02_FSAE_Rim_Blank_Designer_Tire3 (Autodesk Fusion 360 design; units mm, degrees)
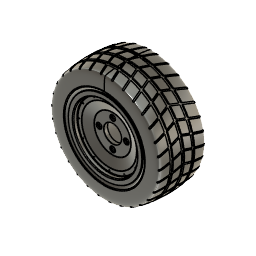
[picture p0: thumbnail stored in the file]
part number: 2026-07-27-09-56-27-671
sketch "Sketch1" plane through (0, 0, 0) normal (1, 0, 0) x axis (0, 1, 0)
  line L1 (153.5, 0) -> (0, 0)
  line L2 (0, 119.5) -> (0, 104)
  line L3 (143.5, 124.5) -> (5, 124.5)
  line L4 (148.5, 134.75) -> (148.5, 129.5)
  line L5 (153.5, 138.25) -> (152, 138.25)
  line L6 (2.5, 119.5) -> (2.5, 104)
  line L7 (143.5, 122) -> (5, 122)
  line L8 (151, 134.75) -> (151, 129.5)
  line L9 (153.5, 135.75) -> (152, 135.75)
  line L10 (2.5, 104) -> (0, 104)
  line L11 (153.5, 135.75) -> (153.5, 138.25)
  arc A1 centre (152, 134.75) radius 3.5 clockwise from (148.5, 134.75) to (152, 138.25)
  arc A2 centre (143.5, 129.5) radius 5 clockwise from (148.5, 129.5) to (143.5, 124.5)
  arc A3 centre (5, 119.5) radius 5 clockwise from (0, 119.5) to (5, 124.5)
  arc A4 centre (5, 119.5) radius 2.5 clockwise from (2.5, 119.5) to (5, 122)
  arc A5 centre (143.5, 129.5) radius 7.5 clockwise from (151, 129.5) to (143.5, 122)
  arc A6 centre (152, 134.75) radius 1 clockwise from (151, 134.75) to (152, 135.75)
  point P1 (0, 0)
  point P2 (0, 0)
  point P4 (0, 104)
  point P3 (153.5, 0)
  point P7 (153.5, 138.25)
  point P6 (148.5, 124.5)
  point P5 (0, 124.5)
  coincident P1 P2
  horizontal L1
  perpendicular L1 L2
  perpendicular L2 L3
  perpendicular L3 L4
  perpendicular L4 L5
  vertical P1 P4
  vertical P3 P7
  tangent L4 A1
  tangent L5 A1
  coincident P6 L3
  coincident P6 L4
  tangent L3 A2
  tangent L4 A2
  coincident P5 L2
  coincident P5 L3
  tangent L2 A3
  tangent L3 A3
  equal A2 A3
  perpendicular L6 L10
  perpendicular L9 L11
  dimension "d1" distance P2 P3 = 153.5
  dimension "d2" = 208
  dimension "d3" = 249
  dimension "d4" = 276.5
  dimension "d5" distance P5 P6 = 148.5
  dimension "d6" radius A1 = 3.5
  dimension "d7" radius A2 = 5
  dimension "d8" = 2.5
revolve "Revolve1" sketch "Sketch1" AlongAngle 360 bodies "FSAE Rim Back"
sketch "Sketch2" plane through (0, 0, 0) normal (0, -1, 0) x axis (1, 0, 0)
  circle C1 centre (0, 0) radius 104
  circle C2 centre (0, 0) radius 119.5
  circle C3 centre (0, 0) radius 112
  circle C4 centre (0, 112) radius 2.15
  point P1 (0, 0)
  point P3 (0, 0)
  point P4 (0, 112)
  coincident P1 P3
  coincident C3 P4
  vertical P3 P4
  dimension "d10" diameter C3 = 224
  dimension "d11" diameter C4 = 4.3
extrude "Extrude1" cut sketch "Sketch2" profile of C4 to an object
circular_pattern "C-Pattern1" TotalAngle 360
canvas "Canvas1"
move "Move1"
sketch "Sketch4" plane through (0, 0, 0) normal (1, 0, 0) x axis (0, 1, 0)
  line L1 (14, 0) -> (0, 0)
  line L2 (14, 72.5) -> (14, 0)
  line L3 (-8, 102.5) -> (14, 72.5)
  line L4 (-8, 124.5) -> (-8, 102.5)
  line L5 (-23.5, 124.5) -> (-8, 124.5)
  line L6 (-23.5, 138) -> (-23.5, 124.5)
  line L7 (-28.25, 138) -> (-23.5, 138)
  line L8 (-28.25, 0) -> (-28.25, 138)
  line L9 (0, 0) -> (-28.25, 0)
  line L10 (-13, 118.1658) -> (-28.25, 119.5)
  line L11 (-13, 102.5) -> (-13, 118.1658)
  line L12 (0, 68.6338) -> (-13, 102.5)
  line L13 (0, 0) -> (0, 68.6338)
  point P1 (0, 0)
  point P2 (0, 0)
  point P11 (0, 0)
  point P12 (-28.25, 119.5)
  point P5 (-8, 102.5)
  point P14 (-13, 102.5)
  point P3 (14, 0)
  point P4 (14, 72.5)
  point P6 (-8, 124.5)
  point P8 (-23.5, 138)
  point P9 (-28.25, 138)
  coincident P1 P2
  horizontal L1
  perpendicular L1 L2
  perpendicular L1 L4
  perpendicular L4 L5
  perpendicular L5 L6
  perpendicular L6 L7
  coincident P1 P11
  collinear L1 L9
  perpendicular L8 L9
  coincident L8 P12
  parallel L8 L11
  vertical L13
  horizontal P5 P14
  dimension "d29" distance P2 P3 = 14
  dimension "d30" = 145
  dimension "d31" = 205
  dimension "d32" = 249
  dimension "d33" = 276
  dimension "d34" distance P4 P6 = 22
  dimension "d35" distance P6 P8 = 15.5
  dimension "d36" distance P8 P9 = 4.75
  dimension "d37" distance L4 L11 = 5
  dimension "d38" angle L12 L13 = 159
  dimension "d39" angle L10 L11 = 95
  dimension "d40" = 239
revolve "Revolve3" sketch "Sketch4" AlongAngle 360 bodies "FSAE Rim Front"
sketch "Sketch5" plane through (0, 0, 0) normal (0, -1, 0) x axis (1, 0, 0)
  circle C1 centre (0, 0) radius 68.6338
  circle C2 centre (0, 0) radius 33
  point P1 (0, 0)
  point P3 (0, 0)
  coincident P1 P3
  dimension "d42" diameter C2 = 66
extrude "Extrude2" cut sketch "Sketch5" profile of C2 to an object
sketch "Sketch6" plane through (0, 0, 0) normal (0, -1, 0) x axis (1, 0, 0)
  circle C1 centre (0, 0) radius 33
  circle C2 centre (0, 0) radius 68.6338
  circle C3 centre (0, 0) radius 50.8
  point P1 (0, 0)
  point P4 (0, 0)
  point P3 (0, 50.8)
  coincident P1 P4
  coincident P3 C3
  vertical P1 P3
  dimension "d45" diameter C3 = 101.6
hole "Hole1" HoleDiameter 10.5 TipAngle 180 CBDepth 5 CBDiameter 20
chamfer "Chamfer2" sketch "Sketch1" distance 0.5
circular_pattern "C-Pattern2" TotalAngle 360
sketch "Sketch7" plane through (0, -13, 0) normal (0, -1, 0) x axis (1, 0, 0)
  circle C1 centre (0, 0) radius 102.5
  circle C2 centre (0, 0) radius 118.1658
  circle C3 centre (0, 0) radius 112
  point P1 (0, 0)
  point P3 (0, 0)
  point P4 (0, 112)
  coincident P1 P3
  coincident C3 P4
  vertical P1 P4
  dimension "d53" diameter C3 = 224
hole "Hole2" HoleDiameter 4.3 TipAngle 180
circular_pattern "C-Pattern3" TotalAngle 360
fillet "Fillet1" radius 1 3 2
chamfer "Chamfer1" distance 0.5
form "Form1"
fillet "Fillet2" radius 5
sketch "Sketch8" plane through (0, 0, 0) normal (1, 0, 0) x axis (0, 1, 0)
  line L1 (47.5, 224.911) -> (47.5, 204.911)
  line L2 (57.5, 224.911) -> (47.5, 224.911)
  line L3 (57.5, 204.9943) -> (57.5, 224.911)
  line L4 (87.5, 224.911) -> (87.5, 204.2438)
  line L5 (97.5, 224.911) -> (87.5, 224.911)
  line L6 (97.5, 203.6595) -> (97.5, 224.911)
  line L7 (17.5, 224.911) -> (17.5, 203.6595)
  line L8 (7.5, 224.911) -> (17.5, 224.911)
  line L9 (7.5, 202.9073) -> (7.5, 224.911)
  arc A1 centre (57.5, -395.0057) radius 600 clockwise from (-46, 196) to (161, 196)
  point P2 (-46, 196)
  point P3 (161, 196)
  point P8 (57.5, 204.9943)
  point P9 (87.5, 204.2438)
  point P12 (97.5, 203.6595)
  point P13 (17.5, 203.6595)
  point P16 (7.5, 202.9073)
  point P5 (47.5, 204.911)
  point P1 (0, 0)
  point P6 (47.5, 224.911)
  point P7 (57.5, 224.911)
  horizontal P2 P3
  vertical L1
  perpendicular L1 L2
  midpoint A1 P8
  perpendicular L2 L3
  coincident A1 P9
  parallel L3 L4
  perpendicular L4 L5
  coincident A1 P12
  perpendicular L5 L6
  coincident A1 P13
  perpendicular L5 L7
  perpendicular L7 L8
  coincident A1 P16
  perpendicular L8 L9
  collinear L2 L8
  collinear L2 L5
  equal L2 L8
  equal L2 L5
  coincident A1 P5
  dimension "d68" radius A1 = 600
  dimension "d69" distance P1 P3 = 196
  dimension "d70" distance P1 P2 = 46
  dimension "d71" distance P1 P3 = 161
  dimension "d73" distance P6 P7 = 10
  dimension "d74" distance L1 L7 = 30
  dimension "d75" distance L3 L4 = 30
  dimension "d76" distance P5 P6 = 20
revolve "Revolve4" AlongAngle 360
revolve "Revolve5" sketch "Sketch8" AlongAngle 360
work_plane "WorkPlane1" AlongDistance 275 ExtraOffset 0
sketch "Sketch9" plane through (0, 0, 275) normal (0, 0, 1) x axis (1, 0, 0)
  line L1 (-48.7008, 53.5011) -> (0, -75.7953)
  line L2 (0, 197.5142) -> (-48.7008, 53.5011)
  line L3 (-43.392, 53.5917) -> (4.6791, -74.0329)
  line L4 (4.7365, 195.9124) -> (-43.392, 53.5917)
  line L5 (4.6791, -74.0329) -> (0, -75.7953)
  line L6 (0, 197.5142) -> (4.7365, 195.9124)
  perpendicular L3 L5
  perpendicular L2 L6
  dimension "d80" = 5
step "SurfaceExtend" extendDistance 125
extrude "Extrude3" cut sketch "Sketch9" to an object
circular_pattern "C-Pattern4" countU 30 TotalAngle 360
named bodies: "FSAE Rim Back", "FSAE Rim Front"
